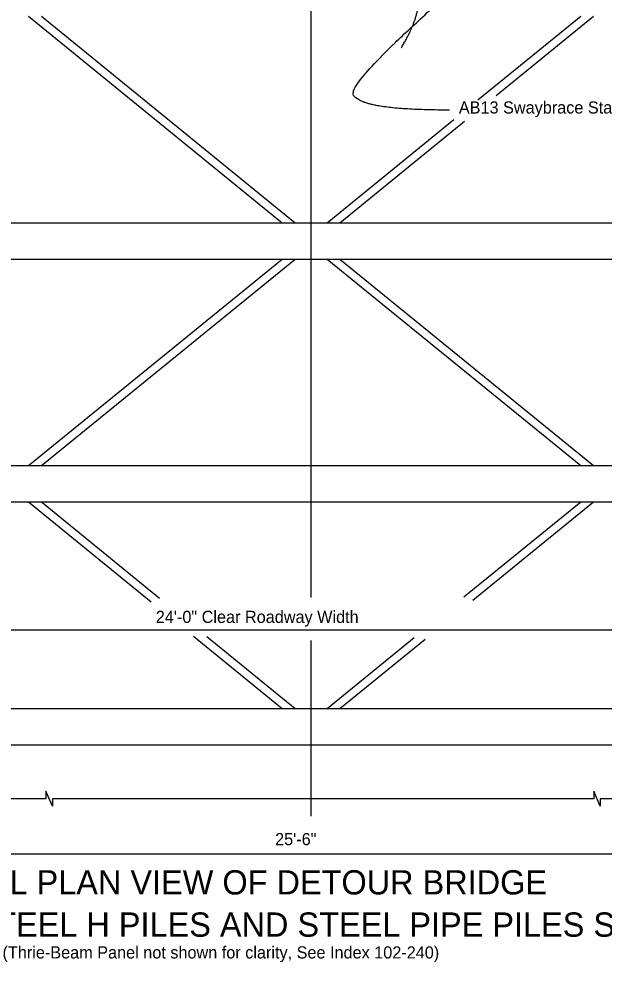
# Model space of a CAD drawing. Extents: x -58 to 62, y 0 to 81.
# Drawn here: x 24.75 to 36.81, y 0.41 to 19.83 of the extents above; entities that cross this region are included whole.
import ezdxf

# ---------------------------------------------------------------- set-up
doc = ezdxf.new("R2010")
doc.units = 0
for name, color, linetype in [('CL_Minor', 7, 'Continuous'), ('Dimension', 7, 'Continuous'), ('SteelMisc_h', 7, 'Continuous'), ('Symbols', 7, 'Continuous'), ('TextStructures', 7, 'Continuous')]:
    doc.layers.add(name, color=color, linetype=linetype)

msp = doc.modelspace()

# ---------------------------------------------------------------- linework, layer by layer
at = {"layer": 'CL_Minor'}
for points in [[(30.77, 7.919), (30.77, 34.382), (30.77, 39.134)], [(30.77, 3.415), (30.77, 7.029)]]:
    msp.add_lwpolyline(points, dxfattribs=at)
at = {"layer": 'Dimension'}
for p, q in [((18.77, 7.249), (42.77, 7.249)), ((16.52, 2.64), (45.02, 2.64))]:
    msp.add_line(p, q, dxfattribs=at)
for points in [[(33.619, 17.953), (31.74, 17.953), (31.538, 18.613), (35.042, 21.607)], [(32.625, 19.232), (32.982, 19.82), (32.982, 20.586), (32.656, 21.633)]]:
    msp.add_open_spline(points, degree=2, dxfattribs=at)
at = {"layer": 'SteelMisc_h'}
for p, q in [((24.953, 19.885), (30.177, 15.635)), ((25.217, 19.885), (30.441, 15.635)), ((34.205, 18.162), (36.323, 19.885)), ((34.584, 18.255), (36.587, 19.885)), ((31.099, 15.635), (33.71, 17.759)), ((31.363, 15.635), (33.932, 17.725)), ((18.312, 15.635), (43.228, 15.635)), ((18.312, 14.885), (43.228, 14.885)), ((24.953, 10.635), (30.177, 14.885)), ((25.217, 10.635), (30.441, 14.885)), ((31.099, 14.885), (36.323, 10.635)), ((31.363, 14.885), (36.587, 10.635)), ((18.312, 10.635), (43.228, 10.635)), ((18.312, 9.885), (43.228, 9.885)), ((24.953, 9.885), (27.477, 7.831)), ((25.217, 9.885), (27.649, 7.906)), ((33.918, 7.928), (36.323, 9.885)), ((34.103, 7.863), (36.587, 9.885)), ((28.349, 7.122), (30.177, 5.635)), ((28.623, 7.113), (30.441, 5.635)), ((31.099, 5.635), (32.895, 7.095)), ((31.363, 5.635), (33.119, 7.063)), ((18.312, 5.635), (43.228, 5.635)), ((18.312, 4.885), (43.228, 4.885))]:
    msp.add_line(p, q, dxfattribs=at)
at = {"layer": 'Symbols'}
for points in [[(30.77, 3.773), (25.441, 3.773), (25.441, 3.618), (25.306, 3.928), (25.306, 3.773), (21.805, 3.773)], [(40.45, 3.773), (36.724, 3.773), (36.724, 3.618), (36.59, 3.928), (36.59, 3.773), (30.77, 3.773)]]:
    msp.add_lwpolyline(points, dxfattribs=at)

# ---------------------------------------------------------------- texts
at = {"layer": 'Dimension'}
for s, p in [('24\'-0" Clear Roadway Width', (27.572, 7.394)), ('25\'-6"', (30.029, 2.818)), ('(Thrie-Beam Panel not shown for clarity, See Index 102-240)', (24.415, 0.485))]:
    msp.add_text(s, height=0.25, dxfattribs=at).set_placement(p)
at = {"layer": 'TextStructures'}
for s, height, p in [('AB13 Swaybrace Standard (Typ.)', 0.25, (33.813, 17.882)), ('TYPICAL PLAN VIEW OF DETOUR BRIDGE', 0.5, (22.144, 1.803)), ('(TIMBER PILES SHOWN, STEEL H PILES AND STEEL PIPE PILES SIMILAR)', 0.5, (15.888, 0.933))]:
    msp.add_text(s, height=height, dxfattribs=at).set_placement(p)

doc.saveas('drawing.dxf')
